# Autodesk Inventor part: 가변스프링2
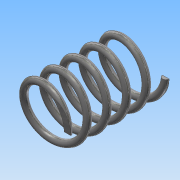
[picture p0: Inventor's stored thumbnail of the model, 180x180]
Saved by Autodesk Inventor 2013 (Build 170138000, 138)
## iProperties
Created: 2018-10
Part Number: 가변스프링2
Material: 스테인리스강
Document SubType Name: Modeling
Designer: Administrator
Density: 8.08 g/cm^3
Mass: 6.28781 g
Surface Area: 15.7884 cm^2
Volume: 0.778194 cm^3
Author: Administrator
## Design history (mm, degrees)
sketch "스케치1"
  geometry: L1 (0, 0)-(0, 29.524); L2 (0, 29.524)-(8, 29.524); L3 (0, 0)-(8, 0); C1 r 1 at (8, 0)
  constraints: 6 end point, 1 centre point, 1 coincident, 1 parallel, 1 perpendicular, 1 vertical
  dimensions: "d0" = 29.52416 distance of L1.start L1.end (derived); "d1" = 8 distance of L1.end L2.end; "d2" = 8 distance of L1.start L3.end; "d3" = 2 diameter of C1
feature "코일1" sketch "스케치1" pitch "d4" = 10; turns "d6" = 5; dims "d5" = 29.52416 (= d0), "d7" = 0, angle "d8" = 90 deg, angle "d9" = 90 deg, "d10" = 0, "d11" = 0
sketch "스케치2"
  geometry: L1 (29.524, 10)-(0, 10); L2 (0, 10)-(0, -10); L3 (0, -10)-(29.524, -10); L4 (29.524, -10)-(29.524, 10); 2 further points
  constraints: 8 end point, 2 parallel, 1 coincident, 1 horizontal, 1 midpoint, 1 perpendicular
  dimensions: "d12" = 20 distance of L3.end L1.start; "d14" = 29.52416 distance of L2.end L3.end (derived)
extrude "돌출1" sketch "스케치2" stored distance "d15" = 0; taper "d16" = 0 deg
node "솔리드1"
